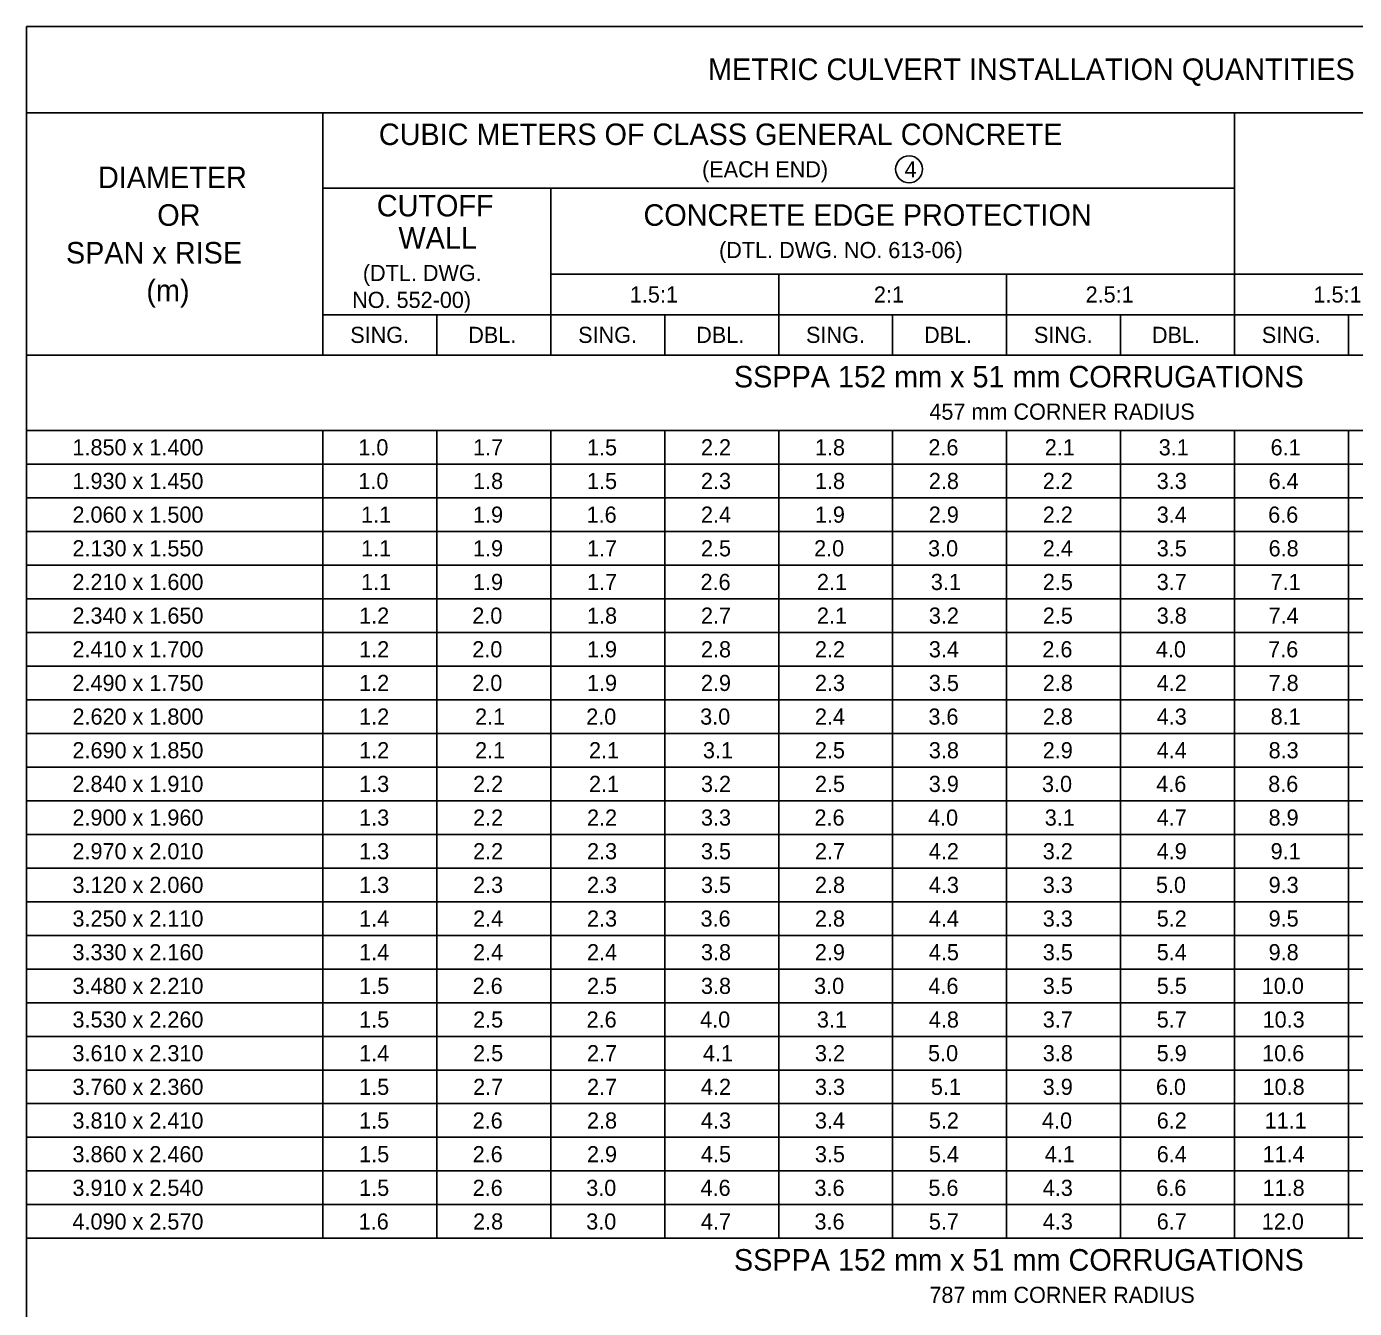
# Model space of a CAD drawing. Extents: x 49991.4 to 50047.6, y 49987.6 to 50011.4.
# Drawn here: x 50039.464 to 50044.395, y 49993.4 to 49998.161 of the extents above; entities that cross this region are included whole.
import ezdxf

# ---------------------------------------------------------------- set-up
doc = ezdxf.new("R2010")
doc.units = 0
doc.layers.add('Level 2', color=7, linetype='Continuous')

msp = doc.modelspace()

# ---------------------------------------------------------------- linework, layer by layer
at = {"layer": 'Level 2'}
for p, q in [((50039.4641, 49998.1607), (50039.4641, 49990.3807)), ((50047.3341, 49998.1607), (50039.4641, 49998.1607)), ((50039.4641, 49997.8407), (50047.3341, 49997.8407)), ((50040.5645, 49997.8407), (50040.5645, 49996.9407)), ((50043.9493, 49997.8407), (50043.9493, 49996.9407)), ((50040.5645, 49997.5607), (50043.9493, 49997.5607)), ((50041.4107, 49997.5607), (50041.4107, 49996.9407)), ((50041.4107, 49997.2407), (50046.4879, 49997.2407)), ((50042.2569, 49997.2407), (50042.2569, 49996.9407)), ((50043.1031, 49997.2407), (50043.1031, 49996.9407)), ((50040.5645, 49997.0907), (50047.3341, 49997.0907)), ((50040.9876, 49997.0907), (50040.9876, 49996.9407)), ((50041.8338, 49997.0907), (50041.8338, 49996.9407)), ((50042.68, 49997.0907), (50042.68, 49996.9407)), ((50043.5262, 49997.0907), (50043.5262, 49996.9407)), ((50044.3724, 49997.0907), (50044.3724, 49996.9407)), ((50039.4641, 49996.9407), (50047.3341, 49996.9407)), ((50039.4641, 49996.6607), (50047.3341, 49996.6607)), ((50040.5645, 49996.6607), (50040.5645, 49993.6607)), ((50040.9876, 49996.6607), (50040.9876, 49993.6607)), ((50041.4107, 49996.6607), (50041.4107, 49993.6607)), ((50041.8338, 49996.6607), (50041.8338, 49993.6607)), ((50042.2569, 49996.6607), (50042.2569, 49993.6607)), ((50042.68, 49996.6607), (50042.68, 49993.6607)), ((50043.1031, 49996.6607), (50043.1031, 49993.6607)), ((50043.5262, 49996.6607), (50043.5262, 49993.6607)), ((50043.9493, 49996.6607), (50043.9493, 49993.6607)), ((50044.3724, 49996.6607), (50044.3724, 49993.6607)), ((50039.4641, 49996.5357), (50047.3341, 49996.5357)), ((50039.4641, 49996.4107), (50047.3341, 49996.4107)), ((50039.4641, 49996.2857), (50047.3341, 49996.2857)), ((50039.4641, 49996.1607), (50047.3341, 49996.1607)), ((50039.4641, 49996.0357), (50047.3341, 49996.0357)), ((50039.4641, 49995.9107), (50047.3341, 49995.9107)), ((50039.4641, 49995.7857), (50047.3341, 49995.7857)), ((50039.4641, 49995.6607), (50047.3341, 49995.6607)), ((50039.4641, 49995.5357), (50047.3341, 49995.5357)), ((50039.4641, 49995.4107), (50047.3341, 49995.4107)), ((50039.4641, 49995.2857), (50047.3341, 49995.2857)), ((50039.4641, 49995.1607), (50047.3341, 49995.1607)), ((50039.4641, 49995.0357), (50047.3341, 49995.0357)), ((50039.4641, 49994.9107), (50047.3341, 49994.9107)), ((50039.4641, 49994.7857), (50047.3341, 49994.7857)), ((50039.4641, 49994.6607), (50047.3341, 49994.6607)), ((50039.4641, 49994.5357), (50047.3341, 49994.5357)), ((50039.4641, 49994.4107), (50047.3341, 49994.4107)), ((50039.4641, 49994.2857), (50047.3341, 49994.2857)), ((50039.4641, 49994.1607), (50047.3341, 49994.1607)), ((50039.4641, 49994.0357), (50047.3341, 49994.0357)), ((50039.4641, 49993.9107), (50047.3341, 49993.9107)), ((50039.4641, 49993.7857), (50047.3341, 49993.7857)), ((50039.4641, 49993.6607), (50047.3341, 49993.6607))]:
    msp.add_line(p, q, dxfattribs=at)
msp.add_circle((50042.7413, 49997.6307), 0.05, dxfattribs=at)

# ---------------------------------------------------------------- texts
for s, height, p in [('METRIC CULVERT INSTALLATION QUANTITIES', 0.08, (50041.9945, 49997.9622)), ('CUBIC METERS OF CLASS GENERAL CONCRETE', 0.08, (50040.7722, 49997.7206)), ('DIAMETER', 0.08, (50039.7294, 49997.5607)), ('(EACH END)', 0.06, (50041.9724, 49997.6007)), ('4', 0.06, (50042.7243, 49997.6007)), ('CUTOFF', 0.08, (50040.7646, 49997.4557)), ('OR', 0.08, (50039.9494, 49997.4207)), ('CONCRETE EDGE PROTECTION', 0.08, (50041.755, 49997.4207)), ('WALL', 0.08, (50040.845, 49997.3357)), ('SPAN x RISE', 0.08, (50039.6103, 49997.2807)), ('(DTL. DWG. NO. 613-06)', 0.06, (50042.0355, 49997.3007)), ('(DTL. DWG.', 0.06, (50040.7128, 49997.2157)), ('(m)', 0.08, (50039.909, 49997.1407)), ('1.5:1', 0.06, (50041.7042, 49997.1357)), ('2:1', 0.06, (50042.6104, 49997.1357)), ('2.5:1', 0.06, (50043.3966, 49997.1357)), ('1.5:1', 0.06, (50044.2428, 49997.1357)), ('NO. 552-00)', 0.06, (50040.6731, 49997.1157)), ('SING.', 0.06, (50040.6661, 49996.9857)), ('DBL.', 0.06, (50041.1044, 49996.9857)), ('SING.', 0.06, (50041.5123, 49996.9857)), ('DBL.', 0.06, (50041.9506, 49996.9857)), ('SING.', 0.06, (50042.3585, 49996.9857)), ('DBL.', 0.06, (50042.7968, 49996.9857)), ('SING.', 0.06, (50043.2047, 49996.9857)), ('DBL.', 0.06, (50043.643, 49996.9857)), ('SING.', 0.06, (50044.0509, 49996.9857)), ('SSPPA 152 mm x 51 mm CORRUGATIONS', 0.08, (50042.0907, 49996.8206)), ('457 mm CORNER RADIUS', 0.06, (50042.8166, 49996.7007)), ('1.850 x 1.400', 0.06, (50039.6346, 49996.5682)), ('1.0', 0.06, (50040.6961, 49996.5682)), ('1.7', 0.06, (50041.1222, 49996.5682)), ('1.5', 0.06, (50041.5453, 49996.5682)), ('2.2', 0.06, (50041.9684, 49996.5682)), ('1.8', 0.06, (50042.3915, 49996.5682)), ('2.6', 0.06, (50042.813, 49996.5682)), ('2.1', 0.06, (50043.2451, 49996.5682)), ('3.1', 0.06, (50043.6682, 49996.5682)), (' 6.1', 0.06, (50044.0613, 49996.5682)), ('1.930 x 1.450', 0.06, (50039.6346, 49996.4432)), ('1.0', 0.06, (50040.6961, 49996.4432)), ('1.8', 0.06, (50041.1222, 49996.4432)), ('1.5', 0.06, (50041.5453, 49996.4432)), ('2.3', 0.06, (50041.9684, 49996.4432)), ('1.8', 0.06, (50042.3915, 49996.4432)), ('2.8', 0.06, (50042.8146, 49996.4432)), ('2.2', 0.06, (50043.2377, 49996.4432)), ('3.3', 0.06, (50043.6608, 49996.4432)), (' 6.4', 0.06, (50044.0539, 49996.4432)), ('2.060 x 1.500', 0.06, (50039.6346, 49996.3182)), ('1.1', 0.06, (50040.7065, 49996.3182)), ('1.9', 0.06, (50041.122, 49996.3182)), ('1.6', 0.06, (50041.5437, 49996.3182)), ('2.4', 0.06, (50041.9684, 49996.3182)), ('1.9', 0.06, (50042.3913, 49996.3182)), ('2.9', 0.06, (50042.8144, 49996.3182)), ('2.2', 0.06, (50043.2377, 49996.3182)), ('3.4', 0.06, (50043.6608, 49996.3182)), (' 6.6', 0.06, (50044.0523, 49996.3182)), ('2.130 x 1.550', 0.06, (50039.6346, 49996.1932)), ('1.1', 0.06, (50040.7065, 49996.1932)), ('1.9', 0.06, (50041.122, 49996.1932)), ('1.7', 0.06, (50041.5453, 49996.1932)), ('2.5', 0.06, (50041.9684, 49996.1932)), ('2.0', 0.06, (50042.3885, 49996.1932)), ('3.0', 0.06, (50042.8116, 49996.1932)), ('2.4', 0.06, (50043.2377, 49996.1932)), ('3.5', 0.06, (50043.6608, 49996.1932)), (' 6.8', 0.06, (50044.0539, 49996.1932)), ('2.210 x 1.600', 0.06, (50039.6346, 49996.0682)), ('1.1', 0.06, (50040.7065, 49996.0682)), ('1.9', 0.06, (50041.122, 49996.0682)), ('1.7', 0.06, (50041.5453, 49996.0682)), ('2.6', 0.06, (50041.9668, 49996.0682)), ('2.1', 0.06, (50042.3989, 49996.0682)), ('3.1', 0.06, (50042.822, 49996.0682)), ('2.5', 0.06, (50043.2377, 49996.0682)), ('3.7', 0.06, (50043.6608, 49996.0682)), (' 7.1', 0.06, (50044.0613, 49996.0682)), ('2.340 x 1.650', 0.06, (50039.6346, 49995.9432)), ('1.2', 0.06, (50040.6991, 49995.9432)), ('2.0', 0.06, (50041.1192, 49995.9432)), ('1.8', 0.06, (50041.5453, 49995.9432)), ('2.7', 0.06, (50041.9684, 49995.9432)), ('2.1', 0.06, (50042.3989, 49995.9432)), ('3.2', 0.06, (50042.8146, 49995.9432)), ('2.5', 0.06, (50043.2377, 49995.9432)), ('3.8', 0.06, (50043.6608, 49995.9432)), (' 7.4', 0.06, (50044.0539, 49995.9432)), ('2.410 x 1.700', 0.06, (50039.6346, 49995.8182)), ('1.2', 0.06, (50040.6991, 49995.8182)), ('2.0', 0.06, (50041.1192, 49995.8182)), ('1.9', 0.06, (50041.5451, 49995.8182)), ('2.8', 0.06, (50041.9684, 49995.8182)), ('2.2', 0.06, (50042.3915, 49995.8182)), ('3.4', 0.06, (50042.8146, 49995.8182)), ('2.6', 0.06, (50043.2361, 49995.8182)), ('4.0', 0.06, (50043.6578, 49995.8182)), (' 7.6', 0.06, (50044.0523, 49995.8182)), ('2.490 x 1.750', 0.06, (50039.6346, 49995.6932)), ('1.2', 0.06, (50040.6991, 49995.6932)), ('2.0', 0.06, (50041.1192, 49995.6932)), ('1.9', 0.06, (50041.5451, 49995.6932)), ('2.9', 0.06, (50041.9682, 49995.6932)), ('2.3', 0.06, (50042.3915, 49995.6932)), ('3.5', 0.06, (50042.8146, 49995.6932)), ('2.8', 0.06, (50043.2377, 49995.6932)), ('4.2', 0.06, (50043.6608, 49995.6932)), (' 7.8', 0.06, (50044.0539, 49995.6932)), ('2.620 x 1.800', 0.06, (50039.6346, 49995.5682)), ('1.2', 0.06, (50040.6991, 49995.5682)), ('2.1', 0.06, (50041.1296, 49995.5682)), ('2.0', 0.06, (50041.5423, 49995.5682)), ('3.0', 0.06, (50041.9654, 49995.5682)), ('2.4', 0.06, (50042.3915, 49995.5682)), ('3.6', 0.06, (50042.813, 49995.5682)), ('2.8', 0.06, (50043.2377, 49995.5682)), ('4.3', 0.06, (50043.6608, 49995.5682)), (' 8.1', 0.06, (50044.0613, 49995.5682)), ('2.690 x 1.850', 0.06, (50039.6346, 49995.4432)), ('1.2', 0.06, (50040.6991, 49995.4432)), ('2.1', 0.06, (50041.1296, 49995.4432)), ('2.1', 0.06, (50041.5527, 49995.4432)), ('3.1', 0.06, (50041.9758, 49995.4432)), ('2.5', 0.06, (50042.3915, 49995.4432)), ('3.8', 0.06, (50042.8146, 49995.4432)), ('2.9', 0.06, (50043.2375, 49995.4432)), ('4.4', 0.06, (50043.6608, 49995.4432)), (' 8.3', 0.06, (50044.0539, 49995.4432)), ('2.840 x 1.910', 0.06, (50039.6346, 49995.3182)), ('1.3', 0.06, (50040.6991, 49995.3182)), ('2.2', 0.06, (50041.1222, 49995.3182)), ('2.1', 0.06, (50041.5527, 49995.3182)), ('3.2', 0.06, (50041.9684, 49995.3182)), ('2.5', 0.06, (50042.3915, 49995.3182)), ('3.9', 0.06, (50042.8144, 49995.3182)), ('3.0', 0.06, (50043.2347, 49995.3182)), ('4.6', 0.06, (50043.6592, 49995.3182)), (' 8.6', 0.06, (50044.0523, 49995.3182)), ('2.900 x 1.960', 0.06, (50039.6346, 49995.1932)), ('1.3', 0.06, (50040.6991, 49995.1932)), ('2.2', 0.06, (50041.1222, 49995.1932)), ('2.2', 0.06, (50041.5453, 49995.1932)), ('3.3', 0.06, (50041.9684, 49995.1932)), ('2.6', 0.06, (50042.3899, 49995.1932)), ('4.0', 0.06, (50042.8116, 49995.1932)), ('3.1', 0.06, (50043.2451, 49995.1932)), ('4.7', 0.06, (50043.6608, 49995.1932)), (' 8.9', 0.06, (50044.0537, 49995.1932)), ('2.970 x 2.010', 0.06, (50039.6346, 49995.0682)), ('1.3', 0.06, (50040.6991, 49995.0682)), ('2.2', 0.06, (50041.1222, 49995.0682)), ('2.3', 0.06, (50041.5453, 49995.0682)), ('3.5', 0.06, (50041.9684, 49995.0682)), ('2.7', 0.06, (50042.3915, 49995.0682)), ('4.2', 0.06, (50042.8146, 49995.0682)), ('3.2', 0.06, (50043.2377, 49995.0682)), ('4.9', 0.06, (50043.6606, 49995.0682)), (' 9.1', 0.06, (50044.0613, 49995.0682)), ('3.120 x 2.060', 0.06, (50039.6346, 49994.9432)), ('1.3', 0.06, (50040.6991, 49994.9432)), ('2.3', 0.06, (50041.1222, 49994.9432)), ('2.3', 0.06, (50041.5453, 49994.9432)), ('3.5', 0.06, (50041.9684, 49994.9432)), ('2.8', 0.06, (50042.3915, 49994.9432)), ('4.3', 0.06, (50042.8146, 49994.9432)), ('3.3', 0.06, (50043.2377, 49994.9432)), ('5.0', 0.06, (50043.6578, 49994.9432)), (' 9.3', 0.06, (50044.0539, 49994.9432)), ('3.250 x 2.110', 0.06, (50039.6346, 49994.8182)), ('1.4', 0.06, (50040.6991, 49994.8182)), ('2.4', 0.06, (50041.1222, 49994.8182)), ('2.3', 0.06, (50041.5453, 49994.8182)), ('3.6', 0.06, (50041.9668, 49994.8182)), ('2.8', 0.06, (50042.3915, 49994.8182)), ('4.4', 0.06, (50042.8146, 49994.8182)), ('3.3', 0.06, (50043.2377, 49994.8182)), ('5.2', 0.06, (50043.6608, 49994.8182)), (' 9.5', 0.06, (50044.0539, 49994.8182)), ('3.330 x 2.160', 0.06, (50039.6346, 49994.6932)), ('1.4', 0.06, (50040.6991, 49994.6932)), ('2.4', 0.06, (50041.1222, 49994.6932)), ('2.4', 0.06, (50041.5453, 49994.6932)), ('3.8', 0.06, (50041.9684, 49994.6932)), ('2.9', 0.06, (50042.3913, 49994.6932)), ('4.5', 0.06, (50042.8146, 49994.6932)), ('3.5', 0.06, (50043.2377, 49994.6932)), ('5.4', 0.06, (50043.6608, 49994.6932)), (' 9.8', 0.06, (50044.0539, 49994.6932)), ('3.480 x 2.210', 0.06, (50039.6346, 49994.5682)), ('1.5', 0.06, (50040.6991, 49994.5682)), ('2.6', 0.06, (50041.1206, 49994.5682)), ('2.5', 0.06, (50041.5453, 49994.5682)), ('3.8', 0.06, (50041.9684, 49994.5682)), ('3.0', 0.06, (50042.3885, 49994.5682)), ('4.6', 0.06, (50042.813, 49994.5682)), ('3.5', 0.06, (50043.2377, 49994.5682)), ('5.5', 0.06, (50043.6608, 49994.5682)), ('10.0', 0.06, (50044.0509, 49994.5682)), ('3.530 x 2.260', 0.06, (50039.6346, 49994.4432)), ('1.5', 0.06, (50040.6991, 49994.4432)), ('2.5', 0.06, (50041.1222, 49994.4432)), ('2.6', 0.06, (50041.5437, 49994.4432)), ('4.0', 0.06, (50041.9654, 49994.4432)), ('3.1', 0.06, (50042.3989, 49994.4432)), ('4.8', 0.06, (50042.8146, 49994.4432)), ('3.7', 0.06, (50043.2377, 49994.4432)), ('5.7', 0.06, (50043.6608, 49994.4432)), ('10.3', 0.06, (50044.0539, 49994.4432)), ('3.610 x 2.310', 0.06, (50039.6346, 49994.3182)), ('1.4', 0.06, (50040.6991, 49994.3182)), ('2.5', 0.06, (50041.1222, 49994.3182)), ('2.7', 0.06, (50041.5453, 49994.3182)), ('4.1', 0.06, (50041.9758, 49994.3182)), ('3.2', 0.06, (50042.3915, 49994.3182)), ('5.0', 0.06, (50042.8116, 49994.3182)), ('3.8', 0.06, (50043.2377, 49994.3182)), ('5.9', 0.06, (50043.6606, 49994.3182)), ('10.6', 0.06, (50044.0523, 49994.3182)), ('3.760 x 2.360', 0.06, (50039.6346, 49994.1932)), ('1.5', 0.06, (50040.6991, 49994.1932)), ('2.7', 0.06, (50041.1222, 49994.1932)), ('2.7', 0.06, (50041.5453, 49994.1932)), ('4.2', 0.06, (50041.9684, 49994.1932)), ('3.3', 0.06, (50042.3915, 49994.1932)), ('5.1', 0.06, (50042.822, 49994.1932)), ('3.9', 0.06, (50043.2375, 49994.1932)), ('6.0', 0.06, (50043.6578, 49994.1932)), ('10.8', 0.06, (50044.0539, 49994.1932)), ('3.810 x 2.410', 0.06, (50039.6346, 49994.0682)), ('2.6', 0.06, (50041.1206, 49994.0682)), ('2.8', 0.06, (50041.5453, 49994.0682)), ('4.3', 0.06, (50041.9684, 49994.0682)), ('3.4', 0.06, (50042.3915, 49994.0682)), ('5.2', 0.06, (50042.8146, 49994.0682)), ('4.0', 0.06, (50043.2347, 49994.0682)), ('6.2', 0.06, (50043.6608, 49994.0682)), ('1.5', 0.06, (50040.6991, 49994.0682)), ('11.1', 0.06, (50044.0613, 49994.0682)), ('3.860 x 2.460', 0.06, (50039.6346, 49993.9432)), ('1.5', 0.06, (50040.6991, 49993.9432)), ('2.6', 0.06, (50041.1206, 49993.9432)), ('2.9', 0.06, (50041.5451, 49993.9432)), ('4.5', 0.06, (50041.9684, 49993.9432)), ('3.5', 0.06, (50042.3915, 49993.9432)), ('5.4', 0.06, (50042.8146, 49993.9432)), ('4.1', 0.06, (50043.2451, 49993.9432)), ('6.4', 0.06, (50043.6608, 49993.9432)), ('11.4', 0.06, (50044.0539, 49993.9432)), ('3.910 x 2.540', 0.06, (50039.6346, 49993.8182)), ('1.5', 0.06, (50040.6991, 49993.8182)), ('2.6', 0.06, (50041.1206, 49993.8182)), ('3.0', 0.06, (50041.5423, 49993.8182)), ('4.6', 0.06, (50041.9668, 49993.8182)), ('3.6', 0.06, (50042.3899, 49993.8182)), ('5.6', 0.06, (50042.813, 49993.8182)), ('4.3', 0.06, (50043.2377, 49993.8182)), ('6.6', 0.06, (50043.6592, 49993.8182)), ('11.8', 0.06, (50044.0539, 49993.8182)), ('4.090 x 2.570', 0.06, (50039.6346, 49993.6932)), ('1.6', 0.06, (50040.6975, 49993.6932)), ('2.8', 0.06, (50041.1222, 49993.6932)), ('3.0', 0.06, (50041.5423, 49993.6932)), ('4.7', 0.06, (50041.9684, 49993.6932)), ('3.6', 0.06, (50042.3899, 49993.6932)), ('5.7', 0.06, (50042.8146, 49993.6932)), ('4.3', 0.06, (50043.2377, 49993.6932)), ('6.7', 0.06, (50043.6608, 49993.6932)), ('12.0', 0.06, (50044.0509, 49993.6932)), ('SSPPA 152 mm x 51 mm CORRUGATIONS', 0.08, (50042.0907, 49993.5406)), ('787 mm CORNER RADIUS', 0.06, (50042.8166, 49993.4207))]:
    msp.add_text(s, height=height, dxfattribs=at).set_placement(p)

doc.saveas('drawing.dxf')
